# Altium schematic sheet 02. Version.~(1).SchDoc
size A3; DocumentNumber: 2; SheetNumber: 2; SheetTotal: 4
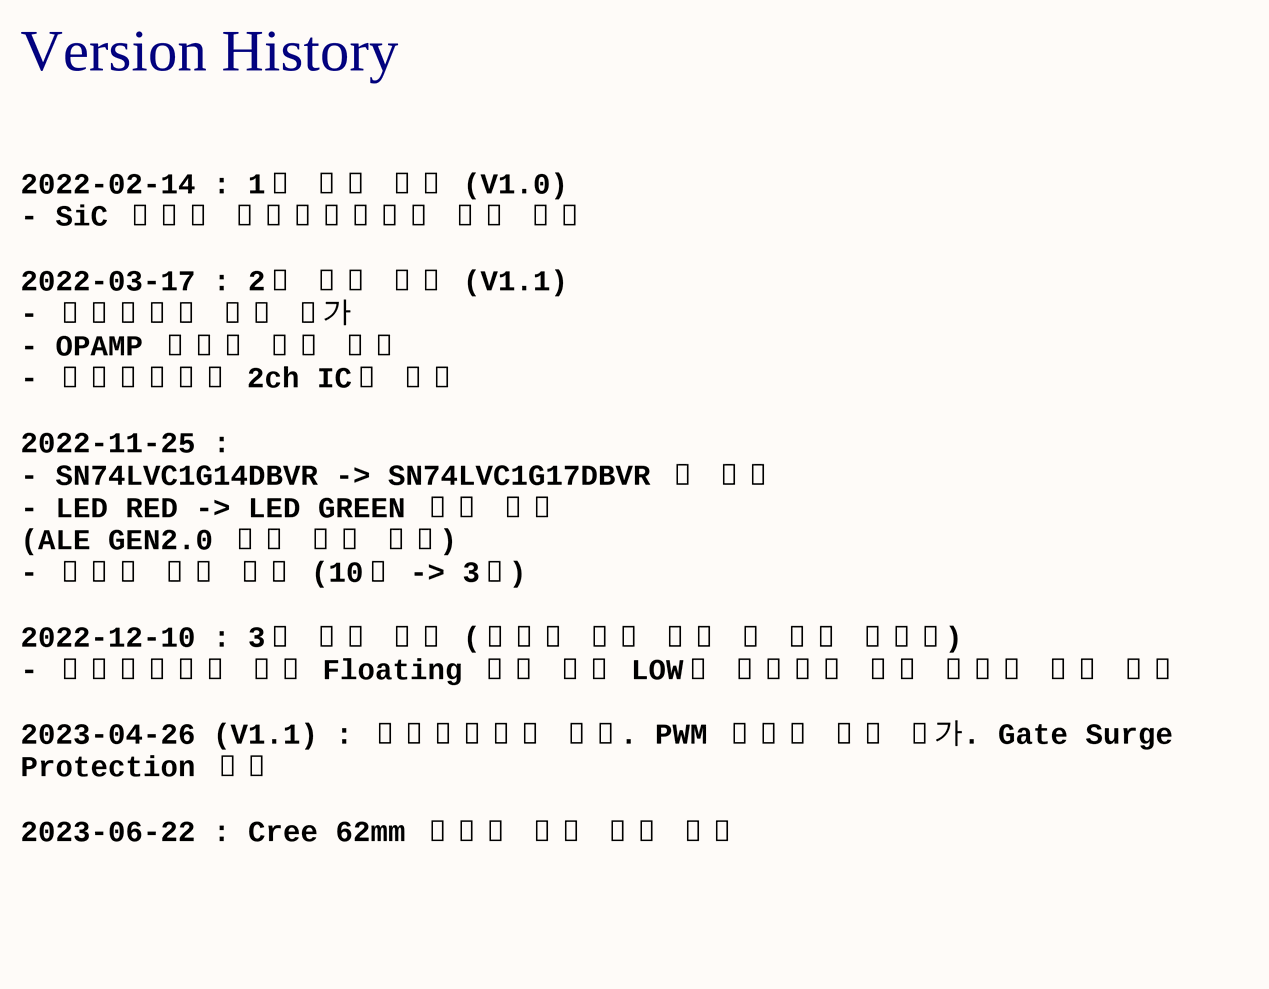
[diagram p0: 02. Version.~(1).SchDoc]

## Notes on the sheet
- Version History
- 2022-02-14 : 1차 회로 설계 (V1.0)
  - SiC 소자용 게이트드라이버 설계 초안
  2022-03-17 : 2차 회로 수정 (V1.1)
  - 레귤레이터 용량 증가
  - OPAMP 전원핀 오류 수정
  - 라인드라이버 2ch IC로 수정
  2022-11-25 :
  - SN74LVC1G14DBVR -> SN74LVC1G17DBVR 로 변경
  - LED RED -> LED GREEN 으로 변경
  (ALE GEN2.0 보드 맞춤 수정)
  - 게이트 저항 수정 (10옴 -> 3옴)
  2022-12-10 : 3차 회로 수정 (시리얼 번호 수정 및 버전 초기화)
  - 라인드라이버 입력 Floating 될때 신호 LOW로 잡히게끔 풀업 풀다운 저항 수정
  2023-04-26 (V1.1) : 입력신호단자 변경. PWM 입력단 필터 추가. Gate Surge Protection 보강
  2023-06-22 : Cree 62mm 소자에 맞춰 설계 변경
